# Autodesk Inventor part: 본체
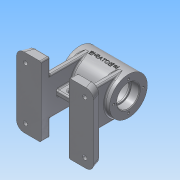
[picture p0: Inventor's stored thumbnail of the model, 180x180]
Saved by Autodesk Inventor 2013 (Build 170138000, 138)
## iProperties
Created: 2016-07
Part Number: 본체
Material: 알루미늄 6061
Document SubType Name: Modeling
Designer: Administrator
Density: 2.71 g/cm^3
Mass: 526.325 g
Surface Area: 538.58 cm^2
Volume: 194.216 cm^3
Author: Administrator
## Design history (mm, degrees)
sketch "스케치1"
  geometry: L1 (-35, 0)-(35, 0); L2 (-35, 0)-(-35, 27); L3 (-35, 27)-(35, 27); L4 (35, 27)-(35, 0); 2 further points
  constraints: 8 end point, 2 perpendicular, 1 coincident, 1 horizontal, 1 midpoint, 1 parallel
  dimensions: "d1" = 70 distance of L1.start L1.end; "d3" = 54 diameter of L3 L1
revolve "회전1" sketch "스케치1" stored, may be unused: angle "d4" = 90 deg
sketch "스케치2"
  geometry: L1 (-35, -27)-(-35, 27) reference; L2 (-35, 27)-(35, 27) reference; L3 (35, 27)-(35, -27) reference; L4 (35, -27)-(-35, -27) reference; L5 (-35, 0)-(35, 0); L6 (-35, 0)-(-35, 16); L7 (-35, 16)-(-23, 16); L8 (-23, 16)-(-23, 14); L9 (-23, 14)-(-21, 14); L10 (-21, 14)-(-21, 22); L11 (-21, 22)-(21, 22); L12 (21, 22)-(21, 14); L13 (21, 14)-(23, 14); L14 (23, 14)-(23, 16); L15 (23, 16)-(35, 16); L16 (35, 0)-(35, 16); 1 further point
  constraints: 24 end point, 6 parallel, 3 perpendicular, 2 midpoint, 2 point on line, 1 collinear
  dimensions: "d7" = 32 diameter of L7 L5; "d9" = 28 diameter of L9 L5; "d10" = 44 diameter of L11 L5; "d11" = 28 diameter of L13 L5; "d12" = 32 diameter of L15 L5; "d13" = 12 distance between parallel lines of L8 L6; "d14" = 2 distance between parallel lines of L10 L8; "d15" = 42 distance between parallel lines of L12 L10; "d16" = 2 distance between parallel lines of L14 L12
revolve "회전2" sketch "스케치2" stored, may be unused: angle "d17" = 90 deg
fillet "모깎기1" dims "d18" = 2
fillet "모깎기2" dims "d19" = 0.3
chamfer "모따기1" distance "d20" = 1; stored, may be unused: second distance "d21" = 2, angle "d22" = 45 deg
node "작업 평면1"
sketch "스케치3"
  geometry: L1 (35, 27)-(35, -27) reference; C1 r 5 at (13, 0); 1 further point
  constraints: 1 centre point, 1 horizontal alignment
  dimensions: "d24" = 10 diameter of C1; "d25" = 22 distance from line of C1.centre L1
extrude "돌출1" join sketch "스케치3" stored distance "d26" = 10; taper "d27" = 0 deg
fillet "모깎기3" dims "d28" = 2
sketch "스케치4"
  geometry: L1 (0, 0)-(-27, 0); L2 (0, 0)-(-25.441, -15.898)
  constraints: 4 end point, 1 horizontal
  dimensions: "d29" = 30 distance of L1.start L2.end; "d30" = 32 deg angle of L2 L1
node "작업 평면2"
sketch "스케치5"
  geometry: C1 r 6 at (0, 0); 1 further point
  constraints: 1 centre point, 1 coincident
  dimensions: "d31" = 12 diameter of C1
extrude "돌출2" join sketch "스케치5" stored distance "d32" = 10; taper "d33" = 0 deg
sketch "스케치15"
  geometry: C1 r 27 at (0, 0) reference; 1 further point
  constraints: 1 vertical alignment
  dimensions: "d63" = 21 distance of C1.centre point (0, 21)
hole "구멍1" sketch "스케치15" at (0, 21) diameter "d64" = 3.242; stored, may be unused: countersink angle "d68" = 90 deg, drill point angle "d70" = 118 deg; dims "d65" = 8, "d66" = 4, "d67" = 2, "d69" = 10
hole "구멍2" diameter "d76" = 5.188; stored, may be unused: countersink angle "d80" = 90 deg, drill point angle "d82" = 118 deg; dims "d74" = 10, "d75" = 10, "d77" = 8, "d78" = 4, "d79" = 2, "d81" = 10
hole "구멍3" diameter "d85" = 5.188; stored, may be unused: countersink angle "d89" = 90 deg, drill point angle "d91" = 118 deg; dims "d83" = 10, "d84" = 10, "d86" = 8, "d87" = 4, "d88" = 2, "d90" = 10
sketch "스케치20"
  geometry: L1 (20, -57)-(20, -70); L2 (20, -70)-(55, -70); L3 (55, -70)-(50.268, -57); L4 (50.268, -57)-(20, -57); 1 further point
  constraints: 8 end point, 2 perpendicular, 1 vertical
  dimensions: "d111" = 70 distance from line of L2 point (0, 0); "d112" = 55 horizontal distance of L2.end point (0, 0); "d113" = 35 distance from line of L2.end L1; "d114" = 13 distance between parallel lines of L2 L4; "d115" = 110 deg angle of L2 L3
extrude "돌출7" join sketch "스케치20" stored distance "d116" = 100; taper "d117" = 0 deg
sketch "스케치21"
  geometry: L1 (0, 0)-(0, 100) reference; L2 (8, 77)-(0, 77); L3 (0, 77)-(0, 23); L4 (0, 23)-(8, 23); L5 (8, 23)-(8, 77); 1 further point
  constraints: 8 end point, 2 parallel, 1 horizontal, 1 perpendicular, 1 point on line
  dimensions: "d118" = 8 distance between parallel lines of L3 L5; "d120" = 27 distance from line of point (-20, 50) L2; "d121" = 54 distance between parallel lines of L4 L2
extrude "돌출8" join sketch "스케치21" stored distance "d122" = 100; taper "d123" = 0 deg
fillet "모깎기4" dims "d124" = 10
fillet "모깎기5" dims "d125" = 2
fillet "모깎기6" dims "d126" = 2
fillet "모깎기7" dims "d127" = 2
sketch "스케치22"
  geometry: L1 (-20, -48)-(20, -48); L2 (-10.406, 22)-(-10.406, 30) reference; L3 (-10.406, 30)-(-8, 30) reference; L4 (-8, 30)-(-8, 29) reference; L5 (-6, 27)-(35, 27) reference; L6 (35, 27)-(35, 22.621) reference; L7 (35, 22.621)-(25, 22.621) reference; L8 (25, 22.621)-(24.026, 21) reference; L9 (24.026, 21)-(25, 19.379) reference; L10 (25, 19.379)-(35, 19.379) reference; L11 (35, 19.379)-(35, 17) reference; L12 (35, 17)-(34, 16) reference; L13 (34, 16)-(23.3, 16) reference; L14 (23, 15.7)-(23, 14) reference; L15 (23, 14)-(21, 14) reference; L16 (21, 14)-(21, 20) reference; L17 (19, 22)-(-10.406, 22) reference; L18 (-35, -17)-(-34, -16) reference; L19 (-34, -16)-(-23.3, -16) reference; L20 (-23, -15.7)-(-23, -14) reference; L21 (-23, -14)-(-21, -14) reference; L22 (-21, -14)-(-21, -20) reference; L23 (-19, -22)-(19, -22) reference; L24 (21, -20)-(21, -14) reference; L25 (21, -14)-(23, -14) reference; L26 (23, -14)-(23, -15.7) reference; L27 (23.3, -16)-(34, -16) reference; L28 (34, -16)-(35, -17) reference; L29 (35, -17)-(35, -19.379) reference; L30 (35, -19.379)-(25, -19.379) reference; L31 (25, -19.379)-(24.026, -21) reference; L32 (24.026, -21)-(25, -22.621) reference; L33 (25, -22.621)-(35, -22.621) reference; L34 (35, -22.621)-(35, -27) reference; L35 (35, -27)-(30, -27) reference; L36 (28, -29)-(28, -55) reference; L37 (30, -57)-(48.868, -57) reference; L38 (50.747, -58.316)-(55, -70) reference; L39 (55, -70)-(20, -70) reference; L40 (20, -70)-(20, -29) reference; L41 (18, -27)-(-18, -27) reference; L42 (-20, -29)-(-20, -70) reference; L43 (-20, -70)-(-55, -70) reference; L44 (-55, -70)-(-50.747, -58.316) reference; L45 (-48.868, -57)-(-30, -57) reference; L46 (-28, -55)-(-28, -29) reference; L47 (-30, -27)-(-35, -27) reference; L48 (-35, -27)-(-35, -22.621) reference; L49 (-35, -22.621)-(-25, -22.621) reference; L50 (-25, -22.621)-(-24.026, -21) reference; L51 (-24.026, -21)-(-25, -19.379) reference; L52 (-25, -19.379)-(-35, -19.379) reference; L53 (-35, -19.379)-(-35, -17) reference; L54 (-34, 16)-(-35, 17) reference; L55 (-35, 17)-(-35, 19.379) reference; L56 (-35, 19.379)-(-25, 19.379) reference; L57 (-25, 19.379)-(-24.026, 21) reference; L58 (-24.026, 21)-(-25, 22.621) reference; L59 (-25, 22.621)-(-35, 22.621) reference; L60 (-35, 22.621)-(-35, 27) reference; L61 (-35, 27)-(-20, 27) reference; L62 (-18, 29)-(-18, 30) reference; L63 (-18, 30)-(-15.594, 30) reference; L64 (-15.594, 30)-(-15.594, 22) reference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; A1 r 0.3 centre (23.3, 15.7) between (23.3, 16) and (23, 15.7) reference; A2 r 2 centre (19, 20) between (21, 20) and (19, 22) reference; A3 r 0.3 centre (-23.3, -15.7) between (-23.3, -16) and (-23, -15.7) reference; A4 r 2 centre (-19, -20) between (-21, -20) and (-19, -22) reference; A5 r 2 centre (19, -20) between (19, -22) and (21, -20) reference; A6 r 0.3 centre (23.3, -15.7) between (23, -15.7) and (23.3, -16) reference; A7 r 2 centre (30, -29) between (30, -27) and (28, -29) reference; A8 r 2 centre (30, -55) between (28, -55) and (30, -57) reference; A9 r 2 centre (48.868, -59) between (50.747, -58.316) and (48.868, -57) reference; A10 r 2 centre (18, -29) between (20, -29) and (18, -27) reference; A11 r 2 centre (-18, -29) between (-18, -27) and (-20, -29) reference; A12 r 2 centre (-48.868, -59) between (-48.868, -57) and (-50.747, -58.316) reference; A13 r 2 centre (-30, -55) between (-30, -57) and (-28, -55) reference; A14 r 2 centre (-30, -29) between (-28, -29) and (-30, -27) reference; A15 r 2 centre (-19, 20) between (-19, 22) and (-21, 20) reference; A16 r 0.3 centre (-23.3, 15.7) between (-23, 15.7) and (-23.3, 16) reference; 1 further point
  constraints: 2 end point, 1 horizontal, 2 other
  dimensions: "d128" = 21 distance between parallel lines of L1 L47
feature "리브1" sketch "스케치22" dims "d129" = 1, "d130" = 8, "d131" = 0, "d132" = 0, "d133" = 1, "d134" = 1
sketch "스케치23"
  geometry: L1 (40, 19.277)-(40, 0) reference; L2 (2, 21.298)-(38, 21.298) reference; L3 (0, 0)-(0, 19.277) reference; L4 (40, 0)-(0, 0) reference; 1 further point
  constraints: 2 other
fillet "모깎기8" dims "d135" = 2
fillet "모깎기9" dims "d136" = 2
sketch "스케치24"
  geometry: L1 (-11.5, -34.5)-(11.5, -34.5); L2 (11.5, -34.5)-(11.5, -41.5); L3 (11.5, -41.5)-(-11.5, -41.5); L4 (-11.5, -41.5)-(-11.5, -34.5); L5 (-11.5, -38)-(11.5, -38); L6 (44.358, -70)-(22, -70) reference; 1 further point
  constraints: 10 end point, 2 midpoint, 2 parallel, 1 horizontal, 1 perpendicular
  dimensions: "d137" = 11.5 distance from line of point (0, 0) L4; "d138" = 23 distance between parallel lines of L2 L4; "d139" = 3.5 distance between parallel lines of L5 L1; "d140" = 32 distance between parallel lines of L6 L5
extrude "돌출9" cut sketch "스케치24" stored distance "d141" = 100; taper "d142" = 0 deg
fillet "모깎기10" dims "d143" = 3.5
fillet "모깎기11" dims "d144" = 2
node "작업 평면5"
sketch "스케치25"
  geometry: L1 (-35, -27)-(-35, 27) reference; 2 further points
  constraints: 1 coincident, 1 other
  dimensions: "d145" = 35 distance from line of L1 point (0, 0) (derived); "d146" = 27 vertical distance of L1.end point (0, 0)
feature "엠보싱1" sketch "스케치25" dims "d12" = 32, "d147" = 0.5, "d148" = 0
sketch "스케치26"
  geometry: L1 (8.513, -10)-(26.868, -10) reference; 3 further points
  dimensions: "d153" = 12.5 distance from line of point (6.368, 2.5) L1; "d154" = 75 distance of point (6.368, 77.5) point (6.368, 2.5); "d155" = 42.5 horizontal distance of point (48.868, 40) point (6.368, 2.5); "d156" = 42.5 horizontal distance of point (48.868, 40) point (6.368, 77.5)
hole "구멍4" sketch "스케치26" at (6.368, 77.5), (6.368, 2.5) diameter "d157" = 6; stored, may be unused: countersink angle "d161" = 90 deg, drill point angle "d163" = 0 deg; dims "d158" = 8, "d159" = 10, "d160" = 4, "d162" = 10
node "솔리드1"
pattern_circular "원형 패턴1" dims angle "d72" = 360 deg
mirror "대칭2"
mirror "대칭3"
mirror "대칭4"
mirror "대칭5"
node "절단 모서리 투영1"
node "절단 모서리 투영4"
